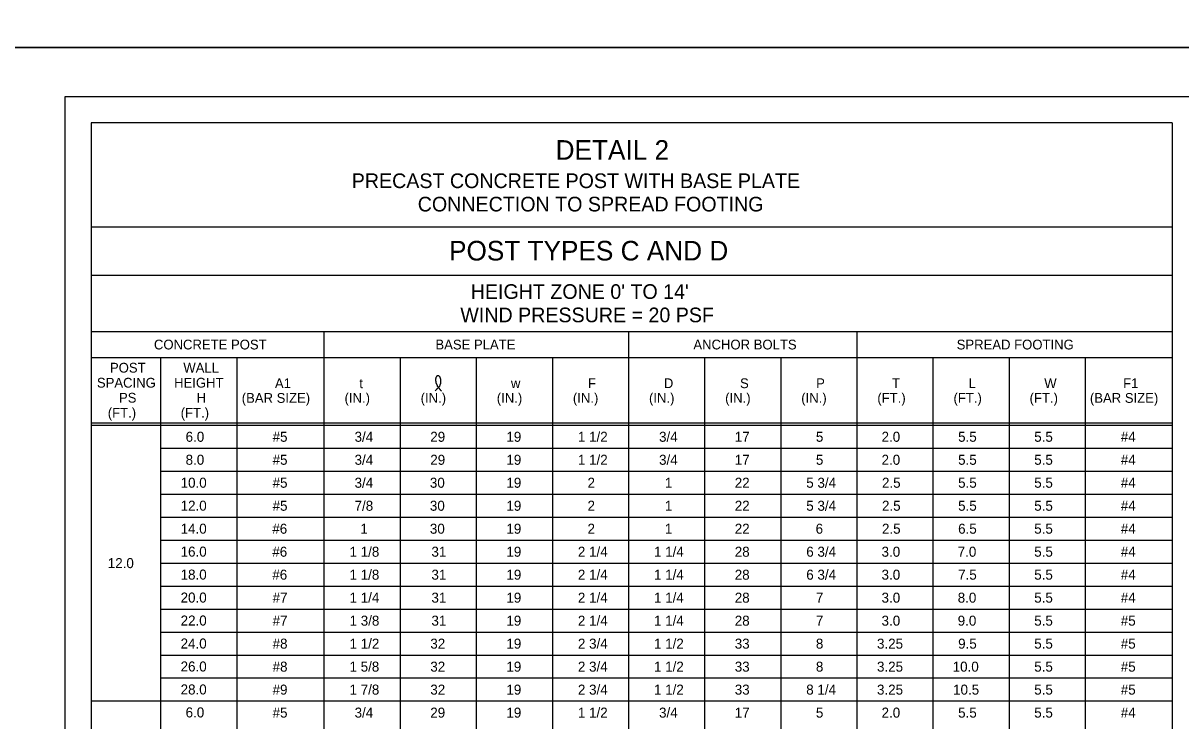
# Model space of a CAD drawing. Extents: x 3351 to 8430, y -3586 to 1457.
# Drawn here: x 6311.5 to 6666.3, y -822.6 to -608.8 of the extents above; entities that cross this region are included whole.
import ezdxf

# ---------------------------------------------------------------- set-up
doc = ezdxf.new("R2010")
doc.units = 0
for name, color, linetype in [('1', 7, 'Continuous'), ('2', 7, 'Continuous'), ('PLT-BNDY', 7, 'Continuous')]:
    doc.layers.add(name, color=color, linetype=linetype)

msp = doc.modelspace()

# ---------------------------------------------------------------- linework, layer by layer
at = {"layer": '1'}
for p, q in [((6332.34, -639.31), (6332.34, -985.5)), ((6663.68, -639.31), (6332.34, -639.31)), ((6663.68, -639.31), (6663.68, -985.5)), ((6663.68, -671.31), (6332.34, -671.31)), ((6332.34, -686.01), (6663.68, -686.01)), ((6332.34, -703.31), (6663.68, -703.31)), ((6332.34, -703.31), (6400.34, -703.31)), ((6332.34, -703.31), (6400.34, -703.31)), ((6332.34, -703.31), (6400.34, -703.31)), ((6403.68, -703.31), (6403.68, -985.5)), ((6497.01, -703.31), (6497.01, -985.5)), ((6567.01, -703.31), (6567.01, -985.5)), ((6332.34, -711.31), (6663.68, -711.31)), ((6353.68, -985.5), (6353.68, -711.31)), ((6377.01, -711.31), (6377.01, -985.5)), ((6427.01, -711.31), (6427.01, -985.5)), ((6450.34, -711.31), (6450.34, -985.5)), ((6473.68, -711.31), (6473.68, -985.5)), ((6520.34, -711.31), (6520.34, -985.5)), ((6543.68, -711.31), (6543.68, -985.5)), ((6590.34, -711.31), (6590.34, -985.5)), ((6613.68, -711.31), (6613.68, -985.5)), ((6637.01, -711.31), (6637.01, -985.5)), ((6332.34, -731.31), (6663.68, -731.31)), ((6332.34, -732.06), (6663.68, -732.06)), ((6390.33, -735.58), (6390.33, -735.58)), ((6415.34, -735.58), (6415.34, -735.58)), ((6438.68, -735.58), (6438.68, -735.58)), ((6462.01, -735.58), (6462.01, -735.58)), ((6485.34, -735.58), (6485.34, -735.58)), ((6508.68, -735.58), (6508.68, -735.58)), ((6532.01, -735.58), (6532.01, -735.58)), ((6555.34, -735.58), (6555.34, -735.58)), ((6578.68, -735.58), (6578.68, -735.58)), ((6602.01, -735.58), (6602.01, -735.58)), ((6625.34, -735.58), (6625.34, -735.58)), ((6650.33, -735.58), (6650.33, -735.58)), ((6353.68, -739.1), (6663.68, -739.1)), ((6353.68, -746.14), (6663.68, -746.14)), ((6353.68, -753.18), (6663.68, -753.18)), ((6353.68, -760.22), (6663.68, -760.22)), ((6353.68, -767.26), (6663.68, -767.26)), ((6353.68, -774.3), (6663.68, -774.3)), ((6353.68, -781.34), (6663.68, -781.34)), ((6353.68, -788.38), (6663.68, -788.38)), ((6353.68, -795.42), (6663.68, -795.42)), ((6353.68, -802.46), (6663.68, -802.46)), ((6353.68, -809.5), (6663.68, -809.5)), ((6332.34, -816.54), (6663.68, -816.54))]:
    msp.add_line(p, q, dxfattribs=at)
msp.add_spline([(6437.73, -721.48), (6437.94, -721.31), (6438.06, -721.18), (6438.26, -720.98), (6438.42, -720.82), (6438.7, -720.61), (6438.9, -720.35), (6439.08, -720.16), (6439.2, -719.93), (6439.3, -719.68), (6439.38, -719.44), (6439.46, -719.21), (6439.49, -719.02), (6439.52, -718.77), (6439.54, -718.55), (6439.52, -718.3), (6439.48, -718.05), (6439.43, -717.81), (6439.37, -717.58), (6439.28, -717.35), (6439.21, -717.22), (6439.11, -717.12), (6439.02, -717.02), (6438.92, -716.94), (6438.81, -716.88), (6438.72, -716.85), (6438.56, -716.85), (6438.46, -716.88), (6438.31, -716.93), (6438.22, -717.01), (6438.16, -717.1), (6438.09, -717.22), (6438.02, -717.33), (6437.98, -717.47), (6437.95, -717.58), (6437.91, -717.82), (6437.89, -717.99), (6437.91, -718.18), (6437.91, -718.38), (6437.95, -718.66), (6437.97, -718.89), (6438.01, -719.06), (6438.08, -719.28), (6438.18, -719.5), (6438.28, -719.7), (6438.37, -719.9), (6438.49, -720.12), (6438.69, -720.3), (6438.81, -720.51), (6438.94, -720.67), (6439.05, -720.85), (6439.2, -721.02), (6439.33, -721.19), (6439.44, -721.3), (6439.55, -721.43), (6439.66, -721.6)], degree=3, dxfattribs=at)
at = {"layer": '2'}
for p, q in [((6324.34, -1195.31), (6324.34, -631.31)), ((6324.34, -631.31), (7110.34, -631.31))]:
    msp.add_line(p, q, dxfattribs=at)
at = {"layer": 'PLT-BNDY'}
for points in [[(6284.34, -22.31), (7125.34, -22.31), (7125.34, -616.31), (6284.34, -616.31)], [(6284.34, -616.31), (7125.34, -616.31), (7125.34, -1210.31), (6284.34, -1210.31)]]:
    msp.add_lwpolyline(points, close=True, dxfattribs=at)

# ---------------------------------------------------------------- texts
at = {"layer": '1'}
for s, height, p in [('DETAIL 2', 6, (6474.69, -650.66)), ('PRECAST CONCRETE POST WITH BASE PLATE', 4.5, (6412.19, -659.36)), ('CONNECTION TO SPREAD FOOTING', 4.5, (6432.42, -666.52)), ('POST TYPES C AND D', 6, (6442.01, -681.54)), ("HEIGHT ZONE 0' TO 14'", 4.5, (6448.66, -693.32)), ('WIND PRESSURE = 20 PSF', 4.5, (6445.47, -700.48)), ('CONCRETE POST', 3, (6351.55, -708.81)), ('BASE PLATE', 3, (6437.84, -708.81)), ('ANCHOR BOLTS', 3, (6516.91, -708.81)), ('SPREAD FOOTING', 3, (6597.63, -708.81)), ('POST', 3, (6338.07, -715.91)), ('WALL', 3, (6360.56, -715.91)), ('SPACING', 3, (6334.07, -720.51)), ('HEIGHT', 3, (6357.73, -720.51)), ('A1', 3, (6388.64, -720.67)), ('t', 3, (6414.51, -720.67)), ('w', 3, (6460.99, -720.67)), ('F', 3, (6484.6, -720.67)), ('D', 3, (6507.87, -720.67)), ('S', 3, (6531.21, -720.67)), ('P', 3, (6554.54, -720.67)), ('T', 3, (6577.82, -720.67)), ('L', 3, (6601.27, -720.67)), ('W', 3, (6624.48, -720.67)), ('F1', 3, (6648.64, -720.67)), ('PS', 3, (6340.83, -725.11)), ('H', 3, (6364.61, -725.11)), ('(BAR SIZE)', 3, (6378.47, -725.17)), ('(IN.)', 3, (6409.98, -725.17)), ('(IN.)', 3, (6433.31, -725.17)), ('(IN.)', 3, (6456.65, -725.17)), ('(IN.)', 3, (6479.98, -725.17)), ('(IN.)', 3, (6503.31, -725.17)), ('(IN.)', 3, (6526.65, -725.17)), ('(IN.)', 3, (6549.98, -725.17)), ('(FT.)', 3, (6573.31, -725.17)), ('(FT.)', 3, (6596.65, -725.17)), ('(FT.)', 3, (6619.98, -725.17)), ('(BAR SIZE)', 3, (6638.47, -725.17)), ('(FT.)', 3, (6337.4, -729.71)), ('(FT.)', 3, (6359.76, -729.71)), ('6.0', 3.07, (6361.26, -737.11)), ('#5', 3.07, (6387.93, -737.11)), ('3/4', 3.07, (6413.06, -737.11)), ('29', 3.07, (6436.26, -737.11)), ('19', 3.07, (6459.59, -737.11)), ('1 1/2', 3.07, (6481.51, -737.11)), ('3/4', 3.07, (6506.39, -737.11)), ('17', 3.07, (6529.6, -737.11)), ('5', 3.07, (6554.47, -737.11)), ('2.0', 3.07, (6574.6, -737.11)), ('5.5', 3.07, (6598.07, -737.11)), ('5.5', 3.07, (6621.4, -737.11)), ('#4', 3.07, (6647.93, -737.11)), ('8.0', 3.07, (6361.26, -744.15)), ('#5', 3.07, (6387.93, -744.16)), ('3/4', 3.07, (6413.06, -744.16)), ('29', 3.07, (6436.26, -744.16)), ('19', 3.07, (6459.59, -744.16)), ('1 1/2', 3.07, (6481.51, -744.16)), ('3/4', 3.07, (6506.39, -744.16)), ('17', 3.07, (6529.6, -744.16)), ('5', 3.07, (6554.47, -744.16)), ('2.0', 3.07, (6574.6, -744.16)), ('5.5', 3.07, (6598.07, -744.16)), ('5.5', 3.07, (6621.4, -744.16)), ('#4', 3.07, (6647.93, -744.16)), ('10.0', 3.07, (6359.73, -751.19)), ('#5', 3.07, (6387.93, -751.2)), ('3/4', 3.07, (6413.06, -751.2)), ('30', 3.07, (6436.14, -751.2)), ('19', 3.07, (6459.59, -751.2)), ('2', 3.07, (6484.47, -751.2)), ('1', 3.07, (6508.16, -751.2)), ('22', 3.07, (6529.6, -751.2)), ('5 3/4', 3.07, (6551.52, -751.2)), ('2.5', 3.07, (6574.73, -751.2)), ('5.5', 3.07, (6598.07, -751.2)), ('5.5', 3.07, (6621.4, -751.2)), ('#4', 3.07, (6647.93, -751.2)), ('12.0', 3.07, (6359.73, -758.23)), ('#5', 3.07, (6387.93, -758.25)), ('7/8', 3.07, (6413.05, -758.25)), ('30', 3.07, (6436.14, -758.25)), ('19', 3.07, (6459.59, -758.25)), ('2', 3.07, (6484.47, -758.25)), ('1', 3.07, (6508.16, -758.25)), ('22', 3.07, (6529.6, -758.25)), ('5 3/4', 3.07, (6551.52, -758.25)), ('2.5', 3.07, (6574.73, -758.25)), ('5.5', 3.07, (6598.07, -758.25)), ('5.5', 3.07, (6621.4, -758.25)), ('#4', 3.07, (6647.93, -758.25)), ('14.0', 3.07, (6359.73, -765.27)), ('#6', 3.07, (6387.84, -765.29)), ('1', 3.07, (6414.82, -765.29)), ('30', 3.07, (6436.14, -765.29)), ('19', 3.07, (6459.59, -765.29)), ('2', 3.07, (6484.47, -765.29)), ('1', 3.07, (6508.16, -765.29)), ('22', 3.07, (6529.6, -765.29)), ('6', 3.07, (6554.39, -765.29)), ('2.5', 3.07, (6574.73, -765.29)), ('6.5', 3.07, (6598.07, -765.29)), ('5.5', 3.07, (6621.4, -765.29)), ('#4', 3.07, (6647.93, -765.29)), ('16.0', 3.07, (6359.73, -772.31)), ('#6', 3.07, (6387.84, -772.34)), ('1 1/8', 3.07, (6411.51, -772.34)), ('31', 3.07, (6436.62, -772.34)), ('19', 3.07, (6459.59, -772.34)), ('2 1/4', 3.07, (6481.51, -772.34)), ('1 1/4', 3.07, (6504.84, -772.34)), ('28', 3.07, (6529.6, -772.34)), ('6 3/4', 3.07, (6551.52, -772.34)), ('3.0', 3.07, (6574.6, -772.34)), ('7.0', 3.07, (6597.94, -772.34)), ('5.5', 3.07, (6621.4, -772.34)), ('#4', 3.07, (6647.93, -772.34)), ('12.0', 3.07, (6337.4, -775.83)), ('18.0', 3.07, (6359.73, -779.35)), ('#6', 3.07, (6387.84, -779.38)), ('1 1/8', 3.07, (6411.51, -779.38)), ('31', 3.07, (6436.62, -779.38)), ('19', 3.07, (6459.59, -779.38)), ('2 1/4', 3.07, (6481.51, -779.38)), ('1 1/4', 3.07, (6504.84, -779.38)), ('28', 3.07, (6529.6, -779.38)), ('6 3/4', 3.07, (6551.52, -779.38)), ('3.0', 3.07, (6574.6, -779.38)), ('7.5', 3.07, (6598.07, -779.38)), ('5.5', 3.07, (6621.4, -779.38)), ('#4', 3.07, (6647.93, -779.38)), ('20.0', 3.07, (6359.73, -786.39)), ('#7', 3.07, (6387.93, -786.42)), ('1 1/4', 3.07, (6411.51, -786.42)), ('31', 3.07, (6436.62, -786.42)), ('19', 3.07, (6459.59, -786.42)), ('2 1/4', 3.07, (6481.51, -786.42)), ('1 1/4', 3.07, (6504.84, -786.42)), ('28', 3.07, (6529.6, -786.42)), ('7', 3.07, (6554.47, -786.42)), ('3.0', 3.07, (6574.6, -786.42)), ('8.0', 3.07, (6597.94, -786.42)), ('5.5', 3.07, (6621.4, -786.42)), ('#4', 3.07, (6647.93, -786.42)), ('22.0', 3.07, (6359.73, -793.43)), ('#7', 3.07, (6387.93, -793.47)), ('1 3/8', 3.07, (6411.52, -793.47)), ('31', 3.07, (6436.62, -793.47)), ('19', 3.07, (6459.59, -793.47)), ('2 1/4', 3.07, (6481.51, -793.47)), ('1 1/4', 3.07, (6504.84, -793.47)), ('28', 3.07, (6529.6, -793.47)), ('7', 3.07, (6554.47, -793.47)), ('3.0', 3.07, (6574.6, -793.47)), ('9.0', 3.07, (6597.94, -793.47)), ('5.5', 3.07, (6621.4, -793.47)), ('#5', 3.07, (6647.93, -793.47)), ('24.0', 3.07, (6359.73, -800.47)), ('#8', 3.07, (6387.93, -800.51)), ('1 1/2', 3.07, (6411.51, -800.51)), ('32', 3.07, (6436.27, -800.51)), ('19', 3.07, (6459.59, -800.51)), ('2 3/4', 3.07, (6481.52, -800.51)), ('1 1/2', 3.07, (6504.84, -800.51)), ('33', 3.07, (6529.6, -800.51)), ('8', 3.07, (6554.47, -800.51)), ('3.25', 3.07, (6573.2, -800.51)), ('9.5', 3.07, (6598.07, -800.51)), ('5.5', 3.07, (6621.4, -800.51)), ('#5', 3.07, (6647.93, -800.51)), ('26.0', 3.07, (6359.73, -807.51)), ('#8', 3.07, (6387.93, -807.56)), ('1 5/8', 3.07, (6411.5, -807.56)), ('32', 3.07, (6436.27, -807.56)), ('19', 3.07, (6459.59, -807.56)), ('2 3/4', 3.07, (6481.52, -807.56)), ('1 1/2', 3.07, (6504.84, -807.56)), ('33', 3.07, (6529.6, -807.56)), ('8', 3.07, (6554.47, -807.56)), ('3.25', 3.07, (6573.2, -807.56)), ('10.0', 3.07, (6596.4, -807.56)), ('5.5', 3.07, (6621.4, -807.56)), ('#5', 3.07, (6647.93, -807.56)), ('28.0', 3.07, (6359.73, -814.55)), ('#9', 3.07, (6387.92, -814.6)), ('1 7/8', 3.07, (6411.51, -814.6)), ('32', 3.07, (6436.27, -814.6)), ('19', 3.07, (6459.59, -814.6)), ('2 3/4', 3.07, (6481.52, -814.6)), ('1 1/2', 3.07, (6504.84, -814.6)), ('33', 3.07, (6529.6, -814.6)), ('8 1/4', 3.07, (6551.51, -814.6)), ('3.25', 3.07, (6573.2, -814.6)), ('10.5', 3.07, (6596.53, -814.6)), ('5.5', 3.07, (6621.4, -814.6)), ('#5', 3.07, (6647.93, -814.6)), ('6.0', 3.07, (6361.26, -821.59)), ('#5', 3.07, (6387.93, -821.65)), ('3/4', 3.07, (6413.06, -821.65)), ('29', 3.07, (6436.26, -821.65)), ('19', 3.07, (6459.59, -821.65)), ('1 1/2', 3.07, (6481.51, -821.65)), ('3/4', 3.07, (6506.39, -821.65)), ('17', 3.07, (6529.6, -821.65)), ('5', 3.07, (6554.47, -821.65)), ('2.0', 3.07, (6574.6, -821.65)), ('5.5', 3.07, (6598.07, -821.65)), ('5.5', 3.07, (6621.4, -821.65)), ('#4', 3.07, (6647.93, -821.65))]:
    msp.add_text(s, height=height, dxfattribs=at).set_placement(p)

doc.saveas('drawing.dxf')
